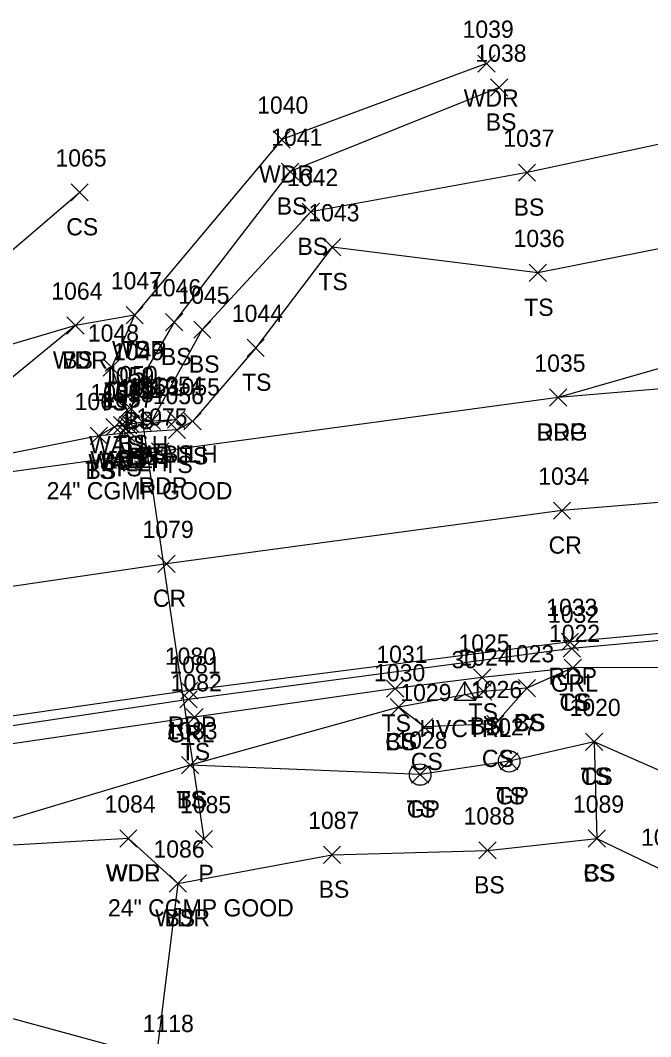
# Model space of a CAD drawing. Extents: x 1502119 to 1504100, y 606168 to 606406.
# Drawn here: x 1503936.5 to 1504009.8, y 606269.9 to 606388 of the extents above; entities that cross this region are included whole.
import ezdxf

# ---------------------------------------------------------------- set-up
doc = ezdxf.new("R2010")
doc.units = 0
for name, color, linetype in [('C_A', 7, 'Continuous'), ('C_I', 7, 'Continuous'), ('CPSM', 7, 'Continuous'), ('D_A', 7, 'Continuous'), ('D_C', 7, 'Continuous'), ('D_I', 7, 'Continuous'), ('D_TIC', 7, 'Continuous'), ('DCP', 7, 'Continuous'), ('DHW', 7, 'Continuous'), ('L_A', 7, 'Continuous'), ('L_I', 7, 'Continuous'), ('L_TIC', 7, 'Continuous'), ('LAWA', 7, 'Continuous'), ('LELB', 7, 'Continuous'), ('P_A', 7, 'Continuous'), ('P_I', 7, 'Continuous'), ('P_TIC', 7, 'Continuous'), ('PET', 7, 'Continuous'), ('PRC', 7, 'Continuous'), ('R_A', 7, 'Continuous'), ('R_I', 7, 'Continuous'), ('R_TIC', 7, 'Continuous'), ('RDG', 7, 'Continuous'), ('RGP', 7, 'Continuous'), ('RGR', 7, 'Continuous')]:
    doc.layers.add(name, color=color, linetype=linetype)

msp = doc.modelspace()

# ---------------------------------------------------------------- linework, layer by layer
at = {"layer": 'CPSM'}
for p, q in [((1503986.96, 606309), (1503988.21, 606311.17)), ((1503989.46, 606309), (1503988.21, 606311.17)), ((1503988.21, 606309.72), (1503988.21, 606311.17)), ((1503986.96, 606309), (1503988.21, 606309.72)), ((1503988.21, 606309.72), (1503988.21, 606309.72)), ((1503988.21, 606309.72), (1503989.46, 606309)), ((1503986.96, 606309), (1503989.46, 606309))]:
    msp.add_line(p, q, dxfattribs=at)
at = {"layer": 'D_TIC'}
for points in [[(1503947.9, 606341.71), (1503949.9, 606343.71)], [(1503949.9, 606341.71), (1503947.9, 606343.71)], [(1503947.82, 606339.62), (1503949.82, 606341.62)], [(1503949.82, 606339.62), (1503947.82, 606341.62)], [(1503948.04, 606339.98), (1503950.04, 606341.98)], [(1503950.04, 606339.98), (1503948.04, 606341.98)], [(1503949.71, 606340.35), (1503951.71, 606342.35)], [(1503951.71, 606340.35), (1503949.71, 606342.35)], [(1503953.63, 606340.62), (1503955.63, 606342.62)], [(1503955.63, 606340.62), (1503953.63, 606342.62)], [(1503956.83, 606291.88), (1503958.83, 606293.88)], [(1503958.83, 606291.88), (1503956.83, 606293.88)]]:
    msp.add_lwpolyline(points, dxfattribs=at)
at = {"layer": 'DCP'}
msp.add_lwpolyline([(1503950.71, 606341.35), (1503957.83, 606292.88)], dxfattribs=at)
at = {"layer": 'DHW'}
for points in [[(1503954.63, 606341.62), (1503948.82, 606340.62)], [(1503948.9, 606342.71), (1503949.04, 606340.98)]]:
    msp.add_lwpolyline(points, dxfattribs=at)
at = {"layer": 'L_TIC'}
for points in [[(1503989.71, 606381.98), (1503991.71, 606383.98)], [(1503991.71, 606381.98), (1503989.71, 606383.98)], [(1503991.19, 606379.2), (1503993.19, 606381.2)], [(1503993.19, 606379.2), (1503991.19, 606381.2)], [(1503965.9, 606373.16), (1503967.9, 606375.16)], [(1503967.9, 606373.16), (1503965.9, 606375.16)], [(1503966.88, 606369.43), (1503968.88, 606371.43)], [(1503968.88, 606369.43), (1503966.88, 606371.43)], [(1503994.43, 606369.31), (1503996.43, 606371.31)], [(1503996.43, 606369.31), (1503994.43, 606371.31)], [(1503942.4, 606367.02), (1503944.4, 606369.02)], [(1503944.4, 606367.02), (1503942.4, 606369.02)], [(1503969.29, 606364.75), (1503971.29, 606366.75)], [(1503971.29, 606364.75), (1503969.29, 606366.75)], [(1503971.76, 606360.65), (1503973.76, 606362.65)], [(1503973.76, 606360.65), (1503971.76, 606362.65)], [(1503995.69, 606357.67), (1503997.69, 606359.67)], [(1503997.69, 606357.67), (1503995.69, 606359.67)], [(1503948.79, 606352.75), (1503950.79, 606354.75)], [(1503950.79, 606352.75), (1503948.79, 606354.75)], [(1503948.79, 606352.75), (1503950.79, 606354.75)], [(1503950.79, 606352.75), (1503948.79, 606354.75)], [(1503941.92, 606351.55), (1503943.92, 606353.55)], [(1503943.92, 606351.55), (1503941.92, 606353.55)], [(1503941.92, 606351.55), (1503943.92, 606353.55)], [(1503943.92, 606351.55), (1503941.92, 606353.55)], [(1503953.4, 606351.94), (1503955.4, 606353.94)], [(1503955.4, 606351.94), (1503953.4, 606353.94)], [(1503956.66, 606351.07), (1503958.66, 606353.07)], [(1503958.66, 606351.07), (1503956.66, 606353.07)], [(1503962.87, 606348.96), (1503964.87, 606350.96)], [(1503964.87, 606348.96), (1503962.87, 606350.96)], [(1503946.12, 606346.67), (1503948.12, 606348.67)], [(1503948.12, 606346.67), (1503946.12, 606348.67)], [(1503949.04, 606344.51), (1503951.04, 606346.51)], [(1503951.04, 606344.51), (1503949.04, 606346.51)], [(1503947.9, 606341.71), (1503949.9, 606343.71)], [(1503949.9, 606341.71), (1503947.9, 606343.71)], [(1503948.38, 606341.84), (1503950.38, 606343.84)], [(1503950.38, 606341.84), (1503948.38, 606343.84)], [(1503946.46, 606339.76), (1503948.46, 606341.76)], [(1503948.46, 606339.76), (1503946.46, 606341.76)], [(1503947.33, 606339.96), (1503949.33, 606341.96)], [(1503949.33, 606339.96), (1503947.33, 606341.96)], [(1503948.04, 606339.98), (1503950.04, 606341.98)], [(1503950.04, 606339.98), (1503948.04, 606341.98)], [(1503948.3, 606340.13), (1503950.3, 606342.13)], [(1503950.3, 606340.13), (1503948.3, 606342.13)], [(1503949.71, 606340.35), (1503951.71, 606342.35)], [(1503951.71, 606340.35), (1503949.71, 606342.35)], [(1503950.81, 606340.47), (1503952.81, 606342.47)], [(1503952.81, 606340.47), (1503950.81, 606342.47)], [(1503950.81, 606340.47), (1503952.81, 606342.47)], [(1503952.81, 606340.47), (1503950.81, 606342.47)], [(1503953.63, 606340.62), (1503955.63, 606342.62)], [(1503955.63, 606340.62), (1503953.63, 606342.62)], [(1503955.53, 606340.41), (1503957.53, 606342.41)], [(1503957.53, 606340.41), (1503955.53, 606342.41)], [(1503944.63, 606338.72), (1503946.63, 606340.72)], [(1503946.63, 606338.72), (1503944.63, 606340.72)], [(1503944.63, 606338.72), (1503946.63, 606340.72)], [(1503946.63, 606338.72), (1503944.63, 606340.72)], [(1503947.8, 606339.02), (1503949.8, 606341.02)], [(1503949.8, 606339.02), (1503947.8, 606341.02)], [(1503953.72, 606339.41), (1503955.72, 606341.41)], [(1503955.72, 606339.41), (1503953.72, 606341.41)], [(1503999.76, 606311.78), (1504001.76, 606313.78)], [(1504001.76, 606311.78), (1503999.76, 606313.78)], [(1503999.76, 606311.78), (1504001.76, 606313.78)], [(1504001.76, 606311.78), (1503999.76, 606313.78)], [(1503989.22, 606310.65), (1503991.22, 606312.65)], [(1503991.22, 606310.65), (1503989.22, 606312.65)], [(1503979.1, 606309.35), (1503981.1, 606311.35)], [(1503981.1, 606309.35), (1503979.1, 606311.35)], [(1503989.34, 606309.02), (1503991.34, 606311.02)], [(1503991.34, 606309.02), (1503989.34, 606311.02)], [(1503994.42, 606309.41), (1503996.42, 606311.41)], [(1503996.42, 606309.41), (1503994.42, 606311.41)], [(1503994.42, 606309.41), (1503996.42, 606311.41)], [(1503996.42, 606309.41), (1503994.42, 606311.41)], [(1503979.5, 606307.2), (1503981.5, 606309.2)], [(1503981.5, 606307.2), (1503979.5, 606309.2)], [(1503979.5, 606307.2), (1503981.5, 606309.2)], [(1503981.5, 606307.2), (1503979.5, 606309.2)], [(1503955.75, 606306.04), (1503957.75, 606308.04)], [(1503957.75, 606306.04), (1503955.75, 606308.04)], [(1503982.47, 606304.9), (1503984.47, 606306.9)], [(1503984.47, 606304.9), (1503982.47, 606306.9)], [(1503990.74, 606305.25), (1503992.74, 606307.25)], [(1503992.74, 606305.25), (1503990.74, 606307.25)], [(1504002.23, 606303.17), (1504004.23, 606305.17)], [(1504004.23, 606303.17), (1504002.23, 606305.17)], [(1504002.23, 606303.17), (1504004.23, 606305.17)], [(1504004.23, 606303.17), (1504002.23, 606305.17)], [(1503992.35, 606300.91), (1503994.35, 606302.91)], [(1503994.35, 606300.91), (1503992.35, 606302.91)], [(1503955.25, 606300.46), (1503957.25, 606302.46)], [(1503957.25, 606300.46), (1503955.25, 606302.46)], [(1503955.25, 606300.46), (1503957.25, 606302.46)], [(1503957.25, 606300.46), (1503955.25, 606302.46)], [(1503982, 606299.37), (1503984, 606301.37)], [(1503984, 606299.37), (1503982, 606301.37)], [(1503948.06, 606291.95), (1503950.06, 606293.95)], [(1503950.06, 606291.95), (1503948.06, 606293.95)], [(1503948.06, 606291.95), (1503950.06, 606293.95)], [(1503950.06, 606291.95), (1503948.06, 606293.95)], [(1504002.55, 606291.94), (1504004.55, 606293.94)], [(1504004.55, 606291.94), (1504002.55, 606293.94)], [(1504002.55, 606291.94), (1504004.55, 606293.94)], [(1504004.55, 606291.94), (1504002.55, 606293.94)], [(1503971.74, 606290.05), (1503973.74, 606292.05)], [(1503973.74, 606290.05), (1503971.74, 606292.05)], [(1503989.82, 606290.56), (1503991.82, 606292.56)], [(1503991.82, 606290.56), (1503989.82, 606292.56)], [(1503953.81, 606286.72), (1503955.81, 606288.72)], [(1503955.81, 606286.72), (1503953.81, 606288.72)], [(1503953.81, 606286.72), (1503955.81, 606288.72)], [(1503955.81, 606286.72), (1503953.81, 606288.72)]]:
    msp.add_lwpolyline(points, dxfattribs=at)
at = {"layer": 'LAWA'}
for points in [[(1503990.71, 606382.98), (1503966.9, 606374.16), (1503949.79, 606353.75), (1503942.92, 606352.55), (1503916.64, 606344.82), (1503911.63, 606340.49), (1503904.12, 606338.88), (1503887.71, 606335.33), (1503868.8, 606333.95), (1503861.91, 606334.62), (1503846, 606330.34), (1503828.45, 606328.53), (1503809.6, 606325.61), (1503789.35, 606322.82), (1503764.11, 606318.67), (1503746.35, 606317.25), (1503727.35, 606312.95), (1503709.14, 606312.53), (1503674.87, 606310.32), (1503655.25, 606308.46), (1503623.87, 606310.46), (1503602.45, 606314.46)], [(1503949.06, 606292.95), (1503922.72, 606291.41), (1503895.88, 606293.14), (1503871.23, 606284.55), (1503848.49, 606280.84), (1503822.63, 606273.75), (1503793.16, 606269.59), (1503770.58, 606267.1), (1503744.52, 606264.72), (1503721.39, 606263.89), (1503714.66, 606265.31), (1503698.22, 606260.24), (1503685.38, 606258.11), (1503660.65, 606259.69), (1503652.68, 606259.1), (1503650.68, 606259.07), (1503643.68, 606257.82), (1503632.11, 606261.1), (1503598.78, 606263.09)], [(1503949.06, 606292.95), (1503954.81, 606287.72), (1503952.28, 606267.45), (1503940.81, 606255.8), (1503930, 606245.46), (1503913.47, 606247.57)]]:
    msp.add_lwpolyline(points, dxfattribs=at)
at = {"layer": 'LELB'}
for points in [[(1504054.41, 606382.91), (1503995.43, 606370.31), (1503970.29, 606365.75), (1503957.66, 606352.07), (1503951.81, 606341.47)], [(1503992.19, 606380.2), (1503967.88, 606370.43), (1503954.4, 606352.94), (1503950.04, 606345.51), (1503949.38, 606342.84), (1503949.3, 606341.13), (1503950.71, 606341.35), (1503951.81, 606341.47), (1503954.63, 606341.62)], [(1504054.79, 606370.18), (1503996.69, 606358.67), (1503972.76, 606361.65), (1503963.87, 606349.96), (1503956.53, 606341.41), (1503954.72, 606340.41), (1503948.8, 606340.02), (1503945.63, 606339.72), (1503928.35, 606336.28), (1503910.71, 606333.69)], [(1503943.4, 606368.02), (1503927.71, 606354.62), (1503916.64, 606344.82)], [(1503949.79, 606353.75), (1503947.12, 606347.67), (1503948.9, 606342.71)], [(1503942.92, 606352.55), (1503928.1, 606340.43), (1503910.71, 606333.69), (1503861.57, 606326.92), (1503811.33, 606319.63), (1503759.93, 606312.02), (1503711.14, 606306.21), (1503662.13, 606303.9), (1503623.99, 606305.38), (1503602.03, 606307.61), (1503601.52, 606307.57), (1503602.45, 606314.46)], [(1503949.04, 606340.98), (1503948.33, 606340.96), (1503947.46, 606340.76), (1503945.63, 606339.72)], [(1504084.2, 606316.18), (1504049.45, 606313.99), (1504016.18, 606312.8), (1504000.76, 606312.78), (1503990.22, 606311.65), (1503980.1, 606310.35), (1503956.75, 606307.04), (1503915.14, 606300.95), (1503869.77, 606289.77), (1503847.82, 606285.43), (1503820.78, 606281.87), (1503792.45, 606279.04), (1503767.54, 606276.84), (1503743.42, 606274.71), (1503718.48, 606272.4), (1503713.68, 606272.36), (1503654.98, 606271.32), (1503649.47, 606271.35), (1503622.06, 606272.76), (1503601.12, 606274.82)], [(1504000.76, 606312.78), (1503995.42, 606310.41), (1503991.74, 606306.25), (1503983.47, 606305.9), (1503980.5, 606308.2)], [(1503995.42, 606310.41), (1503990.34, 606310.02), (1503980.5, 606308.2), (1503956.25, 606301.46)], [(1504016.73, 606298.23), (1504003.23, 606304.17), (1503993.35, 606301.91), (1503983, 606300.37), (1503956.25, 606301.46), (1503922.72, 606291.41)], [(1504003.23, 606304.17), (1504003.55, 606292.94)], [(1503954.81, 606287.72), (1503972.74, 606291.05), (1503990.82, 606291.56), (1504003.55, 606292.94), (1504011.54, 606289.1), (1504016.78, 606269.96), (1504018.73, 606261.72), (1504006.07, 606260.2), (1503984.83, 606255.06)], [(1503984.83, 606255.06), (1503973.29, 606256.69), (1503955.93, 606260.62), (1503952.28, 606267.45), (1503924.4, 606275.03), (1503909.61, 606278), (1503896.78, 606282.99), (1503877.54, 606272.17), (1503862.1, 606272.45), (1503836.9, 606266.22), (1503825.65, 606259.98), (1503818.28, 606261.16), (1503806.2, 606257.22), (1503801.33, 606241.79), (1503784.67, 606238.5), (1503757.1, 606237.25), (1503731.6, 606237.76), (1503710.27, 606237.78), (1503692.02, 606229.45), (1503676.15, 606227.07), (1503663.08, 606221.89), (1503653.08, 606223.12)]]:
    msp.add_lwpolyline(points, dxfattribs=at)
at = {"layer": 'P_TIC'}
for points in [[(1503998.05, 606343.18), (1504000.05, 606345.18)], [(1504000.05, 606343.18), (1503998.05, 606345.18)], [(1503951.76, 606336.92), (1503953.76, 606338.92)], [(1503953.76, 606336.92), (1503951.76, 606338.92)], [(1503998.5, 606330.04), (1504000.5, 606332.04)], [(1504000.5, 606330.04), (1503998.5, 606332.04)], [(1503952.49, 606323.86), (1503954.49, 606325.86)], [(1503954.49, 606323.86), (1503952.49, 606325.86)], [(1503999.43, 606314.8), (1504001.43, 606316.8)], [(1504001.43, 606314.8), (1503999.43, 606316.8)], [(1503955.16, 606309.12), (1503957.16, 606311.12)], [(1503957.16, 606309.12), (1503955.16, 606311.12)]]:
    msp.add_lwpolyline(points, dxfattribs=at)
at = {"layer": 'PET'}
for points in [[(1504085.41, 606349.16), (1504052.4, 606348.69), (1503999.05, 606344.18), (1503952.76, 606337.92), (1503910.76, 606332.19), (1503862.06, 606324.66), (1503811.74, 606316.76), (1503760.3, 606309.68), (1503710.83, 606303.94), (1503662.2, 606301.66), (1503623.65, 606303.36), (1503601.52, 606305.18)], [(1504084.52, 606320.63), (1504050.65, 606320.45), (1504000.43, 606315.8), (1503956.16, 606310.12), (1503915.05, 606304.21), (1503867.85, 606296.91), (1503814.4, 606288.86), (1503766.38, 606281.21), (1503714.75, 606276.43), (1503655.34, 606274.1), (1503622.19, 606275.72), (1503601.58, 606277.52)]]:
    msp.add_lwpolyline(points, dxfattribs=at)
at = {"layer": 'PRC'}
msp.add_lwpolyline([(1504085.68, 606335.47), (1504051.53, 606335.36), (1503999.5, 606331.04), (1503953.49, 606324.86), (1503912.24, 606318.81), (1503865.3, 606311.74), (1503812.8, 606303.34), (1503763.88, 606296.53), (1503711.85, 606290.88), (1503656.36, 606289.42), (1503622.63, 606290.92), (1503602.08, 606292.63)], dxfattribs=at)
at = {"layer": 'R_TIC'}
for points in [[(1503998.05, 606343.18), (1504000.05, 606345.18)], [(1504000.05, 606343.18), (1503998.05, 606345.18)], [(1503999.64, 606314), (1504001.64, 606316)], [(1504001.64, 606314), (1503999.64, 606316)], [(1503955.05, 606308.11), (1503957.05, 606310.11)], [(1503957.05, 606308.11), (1503955.05, 606310.11)]]:
    msp.add_lwpolyline(points, dxfattribs=at)
at = {"layer": 'RDG'}
msp.add_lwpolyline([(1504087.55, 606365.63), (1504053.34, 606359.77), (1503999.05, 606344.18)], dxfattribs=at)
at = {"layer": 'RGP'}
for p, q in [((1503993.35, 606301.91), (1503993.35, 606301.91)), ((1503983, 606300.37), (1503983, 606300.37))]:
    msp.add_line(p, q, dxfattribs=at)
for centre, radius in [((1503993.35, 606301.91), 1.25), ((1503983, 606300.37), 1.25), ((1503993.35, 606301.91), 0.0833), ((1503983, 606300.37), 0.0833)]:
    msp.add_circle(centre, radius, dxfattribs=at)
at = {"layer": 'RGR'}
msp.add_lwpolyline([(1504084.44, 606319.87), (1504050.55, 606319.53), (1504000.64, 606315), (1503956.05, 606309.11), (1503915.05, 606302.99), (1503867.97, 606295.96), (1503814.82, 606287.72), (1503766.2, 606280.53), (1503714.79, 606275.76), (1503655.19, 606273.62), (1503622.1, 606275.05), (1503601.6, 606277)], dxfattribs=at)

# ---------------------------------------------------------------- texts
at = {"layer": 'C_A'}
msp.add_text('HVCTRL', height=2, dxfattribs=at).set_placement((1503982.9, 606304.72))
at = {"layer": 'C_I'}
msp.add_text('30', height=2, dxfattribs=at).set_placement((1503986.65, 606312.72))
at = {"layer": 'D_A'}
for s, p in [('WALLH', (1503944.49, 606337.71)), ('WALLH', (1503950.23, 606336.62)), ('P', (1503950.08, 606336.35)), ('WALLH', (1503944.41, 606335.62)), ('WALLH', (1503944.63, 606335.98)), ('P', (1503957.21, 606287.88))]:
    msp.add_text(s, height=2, dxfattribs=at).set_placement(p)
at = {"layer": 'D_C'}
for p in [(1503939.56, 606332.35), (1503946.69, 606283.88)]:
    msp.add_text('24" CGMP GOOD', height=2, dxfattribs=at).set_placement(p)
at = {"layer": 'D_I'}
for s, p in [('1059', (1503946.12, 606345.71)), ('1052', (1503947.93, 606344.35)), ('1054', (1503951.86, 606344.62)), ('1058', (1503946.04, 606343.62)), ('1060', (1503946.13, 606343.98)), ('1085', (1503955.06, 606295.88))]:
    msp.add_text(s, height=2, dxfattribs=at).set_placement(p)
at = {"layer": 'L_A'}
for s, p in [('WDR', (1503988.07, 606377.98)), ('BS', (1503990.63, 606375.2)), ('WDR', (1503964.26, 606369.16)), ('BS', (1503966.32, 606365.43)), ('BS', (1503993.87, 606365.31)), ('CS', (1503941.84, 606363.02)), ('BS', (1503968.73, 606360.75)), ('TS', (1503971.17, 606356.65)), ('TS', (1503995.1, 606353.67)), ('WDR', (1503947.16, 606348.75)), ('TS', (1503948.2, 606348.75)), ('BS', (1503952.85, 606347.94)), ('WDR', (1503940.28, 606347.55)), ('BS', (1503941.36, 606347.55)), ('BS', (1503956.1, 606347.07)), ('TS', (1503962.28, 606344.96)), ('TS', (1503945.53, 606342.67)), ('BS', (1503948.48, 606340.51)), ('TS', (1503947.31, 606337.71)), ('BS', (1503947.82, 606337.84)), ('BS', (1503947.74, 606336.13)), ('BS', (1503949.15, 606336.35)), ('BS', (1503950.25, 606336.47)), ('BS', (1503950.25, 606336.47)), ('BS', (1503953.08, 606336.62)), ('TS', (1503954.94, 606336.41)), ('BS', (1503945.9, 606335.76)), ('BS', (1503946.77, 606335.96)), ('TS', (1503947.21, 606335.02)), ('BS', (1503947.48, 606335.98)), ('TS', (1503953.13, 606335.41)), ('TS', (1503944.04, 606334.72)), ('BS', (1503944.07, 606334.72)), ('TS', (1503999.16, 606307.78)), ('CS', (1503999.2, 606307.78)), ('TS', (1503988.63, 606306.65)), ('TS', (1503978.51, 606305.35)), ('CS', (1503993.87, 606305.41)), ('BS', (1503993.87, 606305.41)), ('BS', (1503988.78, 606305.02)), ('CS', (1503978.94, 606303.2)), ('BS', (1503978.94, 606303.2)), ('TS', (1503955.16, 606302.04)), ('CS', (1503981.91, 606300.9)), ('CS', (1503990.18, 606301.25)), ('TS', (1504001.64, 606299.17)), ('CS', (1504001.67, 606299.17)), ('TS', (1503954.66, 606296.46)), ('BS', (1503954.69, 606296.46)), ('TS', (1503991.76, 606296.91)), ('TS', (1503981.41, 606295.37)), ('WDR', (1503946.42, 606287.95)), ('WDL', (1503946.48, 606287.95)), ('CS', (1504001.99, 606287.94)), ('BS', (1504001.99, 606287.94)), ('BS', (1503989.26, 606286.56)), ('BS', (1503971.19, 606286.05)), ('WDR', (1503952.17, 606282.72)), ('BS', (1503953.25, 606282.72))]:
    msp.add_text(s, height=2, dxfattribs=at).set_placement(p)
at = {"layer": 'L_I'}
for s, p in [('1039', (1503987.93, 606385.98)), ('1038', (1503989.42, 606383.2)), ('1040', (1503964.04, 606377.16)), ('1041', (1503965.67, 606373.43)), ('1037', (1503992.66, 606373.31)), ('1065', (1503940.58, 606371.02)), ('1042', (1503967.52, 606368.75)), ('1043', (1503969.99, 606364.65)), ('1036', (1503993.86, 606361.67)), ('1047', (1503947.02, 606356.75)), ('1047', (1503947.02, 606356.75)), ('1064', (1503940.1, 606355.55)), ('1064', (1503940.1, 606355.55)), ('1046', (1503951.58, 606355.94)), ('1045', (1503954.88, 606355.07)), ('1044', (1503961.1, 606352.96)), ('1048', (1503944.35, 606350.67)), ('1049', (1503947.26, 606348.51)), ('1059', (1503946.12, 606345.71)), ('1050', (1503946.52, 606345.84)), ('1052', (1503947.93, 606344.35)), ('1053', (1503949.03, 606344.47)), ('1053', (1503949.03, 606344.47)), ('1054', (1503951.86, 606344.62)), ('1055', (1503953.76, 606344.41)), ('1062', (1503944.64, 606343.76)), ('1061', (1503946.08, 606343.96)), ('1060', (1503946.13, 606343.98)), ('1051', (1503947.1, 606344.13)), ('1056', (1503951.9, 606343.41)), ('1063', (1503942.81, 606342.72)), ('1063', (1503942.81, 606342.72)), ('1057', (1503946.03, 606343.02)), ('1022', (1503997.98, 606315.78)), ('1022', (1503997.98, 606315.78)), ('1025', (1503987.45, 606314.65)), ('1031', (1503977.9, 606313.35)), ('1024', (1503987.57, 606313.02)), ('1023', (1503992.65, 606313.41)), ('1023', (1503992.65, 606313.41)), ('1082', (1503953.98, 606310.04)), ('1030', (1503977.64, 606311.2)), ('1030', (1503977.64, 606311.2)), ('1029', (1503980.69, 606308.9)), ('1026', (1503988.91, 606309.25)), ('1020', (1504000.37, 606307.17)), ('1020', (1504000.37, 606307.17)), ('1083', (1503953.48, 606304.46)), ('1083', (1503953.48, 606304.46)), ('1027', (1503990.58, 606304.91)), ('1028', (1503980.23, 606303.37)), ('1084', (1503946.29, 606295.95)), ('1084', (1503946.29, 606295.95)), ('1089', (1504000.77, 606295.94)), ('1089', (1504000.77, 606295.94)), ('1087', (1503969.97, 606294.05)), ('1088', (1503988.05, 606294.56)), ('1090', (1504008.69, 606292.1)), ('1086', (1503951.98, 606290.72)), ('1086', (1503951.98, 606290.72)), ('1118', (1503950.73, 606270.45)), ('1118', (1503950.73, 606270.45)), ('1118', (1503950.73, 606270.45))]:
    msp.add_text(s, height=2, dxfattribs=at).set_placement(p)
at = {"layer": 'P_A'}
for s, p in [('RDP', (1503996.54, 606339.18)), ('RDP', (1503950.25, 606332.92)), ('CR', (1503997.94, 606326.04)), ('CR', (1503951.92, 606319.86)), ('RDP', (1503997.92, 606310.8)), ('RDP', (1503953.65, 606305.12))]:
    msp.add_text(s, height=2, dxfattribs=at).set_placement(p)
at = {"layer": 'P_I'}
for s, p in [('1035', (1503996.28, 606347.18)), ('1075', (1503949.99, 606340.92)), ('1034', (1503996.73, 606334.04)), ('1079', (1503950.71, 606327.86)), ('1033', (1503997.66, 606318.8)), ('1080', (1503953.3, 606313.12))]:
    msp.add_text(s, height=2, dxfattribs=at).set_placement(p)
at = {"layer": 'R_A'}
for s, p in [('DRG', (1503996.54, 606339.18)), ('GRL', (1503998.18, 606310)), ('GRL', (1503953.59, 606304.11)), ('GP', (1503991.79, 606296.91)), ('GP', (1503981.44, 606295.37))]:
    msp.add_text(s, height=2, dxfattribs=at).set_placement(p)
at = {"layer": 'R_I'}
for s, p in [('1035', (1503996.28, 606347.18)), ('1032', (1503997.87, 606318)), ('1081', (1503953.84, 606312.11)), ('1027', (1503990.58, 606304.91)), ('1028', (1503980.23, 606303.37))]:
    msp.add_text(s, height=2, dxfattribs=at).set_placement(p)

doc.saveas('drawing.dxf')
